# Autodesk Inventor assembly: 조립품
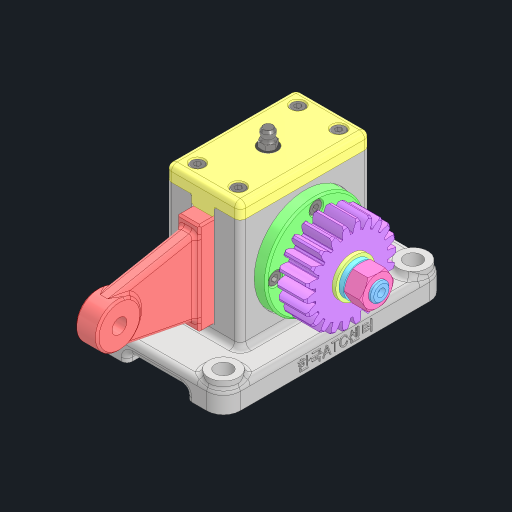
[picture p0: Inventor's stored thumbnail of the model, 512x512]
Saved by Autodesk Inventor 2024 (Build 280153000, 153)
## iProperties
Created: 2025-04
Part Number: 조립품
Document SubType Name: Assembly
Designer: kh_501
Author: kh_501
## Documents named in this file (15)
- C:\Users\kh_501\Desktop\750404V1008\조립품.iam
- C:\Users\kh_501\Desktop\750404V1008\본체.ipt
- C:\Users\kh_501\Desktop\750404V1008\그리스 니플 M6x0.75\그리스 니플 M6x0.75.ipt
- C:\Users\kh_501\Desktop\750404V1008\로드\로드.ipt
- C:\Users\kh_501\Desktop\750404V1008\스퍼기어\스퍼기어.ipt
- C:\Users\kh_501\Desktop\750404V1008\스프링와셔 M10\스프링와셔 M10.ipt
- C:\Users\kh_501\Desktop\750404V1008\실링\실링.ipt
- C:\Users\kh_501\Desktop\750404V1008\앞커버\앞커버.ipt
- C:\Users\kh_501\Desktop\750404V1008\윗커버\윗커버.ipt
- C:\Users\kh_501\Desktop\750404V1008\육각 너트 M10\육각 너트 M10.ipt
- C:\Users\kh_501\Desktop\750404V1008\육각 소켓 머리 볼트 M4x10\육각 소켓 머리 볼트 M4x10.ipt
- C:\Users\kh_501\Desktop\750404V1008\편심축\편심축.ipt
- C:\Users\kh_501\Desktop\750404V1008\평와셔 M10\평와셔 M10.ipt
- C:\Users\kh_501\Desktop\750404V1008\평행키 4x4x10\평행키 4x4x10.ipt
- C:\Users\kh_501\Desktop\750404V1008\플랜지 오일레스 부시\플랜지 오일레스 부시.ipt
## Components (3 placed, 2 different names)
1. 그리스 니플 M6x0.75:1 — 각도:4
2. 플랜지 오일레스 부시:1 — 각도:9
3. 플랜지 오일레스 부시:2 — 각도:10
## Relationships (3: Angle 3)
- 각도:4 [Angle]: 그리스 니플 M6x0.75:1
- 각도:9 [Angle]: 플랜지 오일레스 부시:1
- 각도:10 [Angle]: 플랜지 오일레스 부시:2
